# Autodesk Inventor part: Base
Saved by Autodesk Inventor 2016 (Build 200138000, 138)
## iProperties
Created: 2016-01
Part Number: Base
Material: Generic
Document SubType Name: Modeling
Designer: John
Density: 1 g/cm^3
Appearance: Default
Author: John
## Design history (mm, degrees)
feature "SOLID1"
body "Solid1"
